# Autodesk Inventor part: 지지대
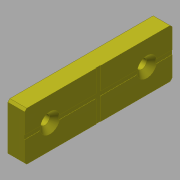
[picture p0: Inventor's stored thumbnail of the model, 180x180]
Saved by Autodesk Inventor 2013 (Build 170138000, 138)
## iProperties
Created: 2017-04
Part Number: 지지대
Material: 강철
Document SubType Name: Modeling
Designer: mduedu
Density: 7.85 g/cm^3
Mass: 97.8484 g
Surface Area: 48.4895 cm^2
Volume: 12.4648 cm^3
Author: mduedu
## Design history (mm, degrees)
sketch "스케치1"
  geometry: L1 (23, -35)-(23, 35); L2 (0, -35)-(0, 35); L3 (0, 35)-(23, 35); L4 (0, -35)-(23, -35); 2 further points
  constraints: 8 end point, 2 parallel, 1 coincident, 1 midpoint, 1 perpendicular, 1 vertical
  dimensions: "d1" = 23 distance between parallel lines of L2 L1; "d15" = 70 distance of L1.start L1.end
extrude "돌출1" new body sketch "스케치1" distance "d2" = 8; taper "d3" = 0 deg
chamfer "모따기2" distance "d16" = 1; stored, may be unused: second distance "d17" = 2, angle "d18" = 45 deg
sketch "스케치2"
  geometry: L1 (1, -35)-(22, -35) reference; L2 (23, -34)-(23, 34) reference; L3 (22, 35)-(1, 35) reference; L4 (0, 34)-(0, -34) reference; L5 (11.5, 35)-(11.5, -35); L6 (23, 0)-(0, 0); L7 (1, -35)-(0, -34) reference; L8 (23, -34)-(22, -35) reference; L9 (22, 35)-(23, 34) reference; L10 (0, 34)-(1, 35) reference; 2 further points
  constraints: 4 end point, 4 midpoint, 1 point on line, 1 symmetric about line
  dimensions: "d7" = 12 distance from line of point (11.5, 23) L3
  node "투영된 루프1"
sketch "스케치3"
  geometry: 4 further points
  constraints: 2 coincident
hole "구멍1" sketch "스케치3" at (11.5, 23), (11.5, -23) diameter "d8" = 4.5; stored, may be unused: countersink angle "d12" = 90 deg, drill point angle "d14" = 0 deg; dims "d9" = 6, "d10" = 9.4, "d11" = 2, "d13" = 8
sketch "스케치4"
  geometry: L1 (-35, 22)-(-35, 1) reference; L2 (35, 1)-(35, 22) reference; L3 (34, 23)-(-34, 23) reference; L4 (-34, 0)-(34, 0) reference; L5 (-35, 11.5)-(35, 11.5); L6 (0, 23)-(0, 0); L7 (-35, 12.5)-(35, 12.5); L8 (-35, 10.5)-(35, 10.5); L9 (-1, 23)-(-1, 0); L10 (1, 23)-(1, 0)
  constraints: 12 end point, 8 point on line, 4 parallel, 3 midpoint, 3 perpendicular
  dimensions: "d19" = 1 distance between parallel lines of L7 L5; "d21" = 1 distance between parallel lines of L8 L5; "d22" = 1 distance between parallel lines of L9 L6; "d23" = 1 distance between parallel lines of L10 L6
extrude "돌출2" cut sketch "스케치4" distance "d24" = 0.2; taper "d25" = 0 deg
extrude "돌출3" cut sketch "스케치4" distance "d26" = 0.2; taper "d27" = 0 deg
fillet "모깎기1" dims "d28" = 0.2
node "솔리드2"
node "솔리드1"
